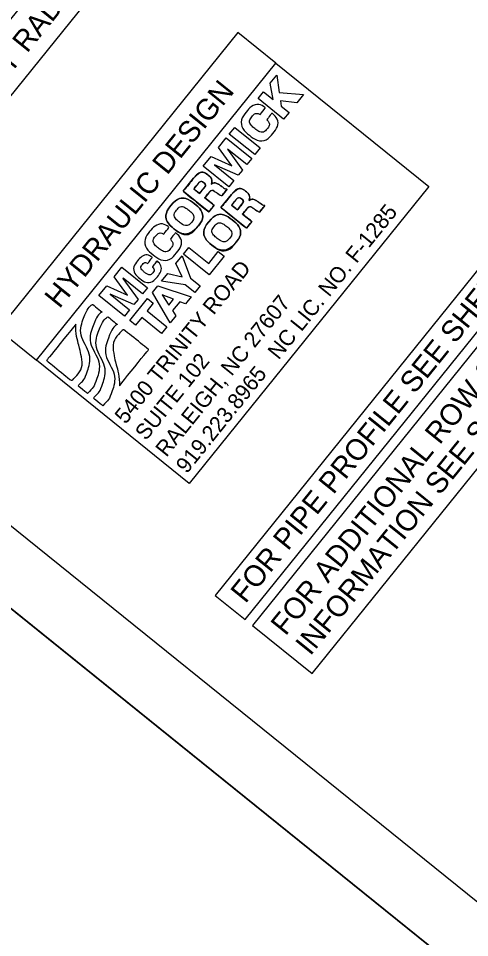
# Model space of a CAD drawing. Extents: x 1487875 to 1489967, y 498345 to 500495.
# Drawn here: x 1489508.5 to 1489628.3, y 499770.6 to 500014.7 of the extents above; entities that cross this region are included whole.
import ezdxf

# ---------------------------------------------------------------- set-up
doc = ezdxf.new("R2010")
doc.units = 0
for name, color, linetype in [('Exist Utilities Gas UG Line SUE LOS B', 7, 'Continuous'), ('Exist Utilities TV UG Cable SUE LOS C', 7, 'Continuous'), ('Exist Utilities Water Fire Hydrant CELL', 7, 'Continuous'), ('Exist Utilities Water Meter CELL', 7, 'Continuous'), ('Prop UG Pow Cables', 7, 'Continuous')]:
    doc.layers.add(name, color=color, linetype=linetype)

msp = doc.modelspace()

# ---------------------------------------------------------------- linework, layer by layer
at = {"layer": 'Exist Utilities TV UG Cable SUE LOS C'}
for points in [[(1488938.86, 500315.83), (1487997.21, 499148.18), (1488814.55, 498489.05), (1489756.18, 499656.68)], [(1488814.55, 498489.05), (1487997.21, 499148.15), (1488813.25, 500160.1), (1488842.5, 500136.51), (1488968.06, 500292.24), (1489756.18, 499656.68)]]:
    msp.add_lwpolyline(points, close=True, dxfattribs=at)
at = {"layer": 'Exist Utilities Water Fire Hydrant CELL'}
msp.add_lwpolyline([(1488842.5, 500136.51), (1488813.25, 500160.1), (1488087.84, 499260.53), (1488879.09, 498569.08), (1489756.18, 499656.68), (1488968.06, 500292.24)], close=True, dxfattribs=at)
msp.add_lwpolyline([(1488842.5, 500136.51), (1488813.25, 500160.1), (1488087.84, 499260.53), (1488879.09, 498569.08), (1489756.18, 499656.68), (1488968.06, 500292.24)], close=True, dxfattribs=at)
at = {"layer": 'Exist Utilities Water Meter CELL'}
for p, q in [((1489575.33, 499997.5), (1489577.1, 499999.7)), ((1489577.1, 499999.7), (1489577.75, 499995.03)), ((1489576.13, 499993.16), (1489575.33, 499997.5)), ((1489572.1, 499993.49), (1489573.53, 499995.26)), ((1489578.89, 499988.01), (1489572.1, 499993.49)), ((1489573.53, 499995.26), (1489576.13, 499993.16)), ((1489577.75, 499995.03), (1489584.15, 499994.53)), ((1489584.15, 499994.53), (1489582.38, 499992.33)), ((1489582.38, 499992.33), (1489578.05, 499992.81)), ((1489578.05, 499992.81), (1489578.23, 499991.47)), ((1489578.23, 499991.47), (1489580.32, 499989.78)), ((1489580.32, 499989.78), (1489578.89, 499988.01)), ((1489564.47, 499984.03), (1489565.9, 499985.8)), ((1489565.9, 499985.8), (1489572.69, 499980.32)), ((1489571.26, 499978.55), (1489564.47, 499984.03)), ((1489561.57, 499980.43), (1489563.67, 499983.04)), ((1489563.67, 499983.04), (1489570.46, 499977.56)), ((1489565.15, 499975.61), (1489561.57, 499980.43)), ((1489563.96, 499980.05), (1489563.95, 499980.03)), ((1489563.95, 499980.03), (1489567.95, 499974.45)), ((1489569.12, 499975.89), (1489563.96, 499980.05)), ((1489572.69, 499980.32), (1489571.26, 499978.55)), ((1489557.56, 499975.46), (1489559.66, 499978.07)), ((1489559.66, 499978.07), (1489565.14, 499975.59)), ((1489560.56, 499975.83), (1489560.54, 499975.81)), ((1489560.54, 499975.81), (1489565.7, 499971.65)), ((1489566.86, 499973.1), (1489560.56, 499975.83)), ((1489570.46, 499977.56), (1489569.12, 499975.89)), ((1489564.36, 499969.98), (1489557.56, 499975.46)), ((1489565.14, 499975.59), (1489565.15, 499975.61)), ((1489567.95, 499974.45), (1489566.86, 499973.1)), ((1489565.7, 499971.65), (1489564.36, 499969.98)), ((1489559.67, 499970.68), (1489559.69, 499970.67)), ((1489563.88, 499969.39), (1489562.47, 499967.64)), ((1489569.72, 499966.35), (1489569.74, 499966.33)), ((1489573.92, 499965.06), (1489572.51, 499963.31)), ((1489552.29, 499952.15), (1489553.72, 499953.92)), ((1489553.72, 499953.92), (1489558.99, 499949.66)), ((1489550.3, 499949.67), (1489551.92, 499951.68)), ((1489551.92, 499951.68), (1489554.18, 499945.77)), ((1489559.09, 499946.67), (1489552.29, 499952.15)), ((1489558.99, 499949.66), (1489561.55, 499952.83)), ((1489563.07, 499951.61), (1489559.09, 499946.67)), ((1489561.55, 499952.83), (1489563.07, 499951.61)), ((1489551.97, 499946.09), (1489550.3, 499949.67)), ((1489533.86, 499946.08), (1489535.97, 499948.69)), ((1489535.97, 499948.69), (1489542.76, 499943.21)), ((1489546.5, 499944.96), (1489548.12, 499946.97)), ((1489548.12, 499946.97), (1489551.97, 499946.09)), ((1489537.45, 499941.25), (1489533.86, 499946.08)), ((1489536.26, 499945.7), (1489536.24, 499945.68)), ((1489536.24, 499945.68), (1489540.25, 499940.09)), ((1489541.42, 499941.54), (1489536.26, 499945.7)), ((1489552.76, 499944), (1489546.5, 499944.96)), ((1489554.18, 499945.77), (1489556.72, 499943.72)), ((1489529.86, 499941.11), (1489531.96, 499943.72)), ((1489531.96, 499943.72), (1489537.43, 499941.24)), ((1489542.76, 499943.21), (1489541.42, 499941.54)), ((1489544.04, 499941.91), (1489545.49, 499943.71)), ((1489548.78, 499933.89), (1489544.04, 499941.91)), ((1489545.49, 499943.71), (1489554.33, 499940.77)), ((1489555.29, 499941.95), (1489552.76, 499944)), ((1489556.72, 499943.72), (1489555.29, 499941.95)), ((1489536.65, 499935.63), (1489529.86, 499941.11)), ((1489532.85, 499941.47), (1489532.84, 499941.46)), ((1489532.84, 499941.46), (1489537.99, 499937.3)), ((1489539.16, 499938.74), (1489532.85, 499941.47)), ((1489537.43, 499941.24), (1489537.45, 499941.25)), ((1489538.06, 499934.49), (1489542.76, 499940.32)), ((1489540.25, 499940.09), (1489539.16, 499938.74)), ((1489542.76, 499940.32), (1489544.28, 499939.09)), ((1489546.65, 499941.29), (1489546.64, 499941.28)), ((1489546.64, 499941.28), (1489548.39, 499938.59)), ((1489549.64, 499940.13), (1489546.65, 499941.29)), ((1489548.39, 499938.59), (1489549.64, 499940.13)), ((1489551.29, 499939.49), (1489549.38, 499937.12)), ((1489552.84, 499938.92), (1489551.29, 499939.49)), ((1489554.33, 499940.77), (1489552.84, 499938.92)), ((1489537.99, 499937.3), (1489536.65, 499935.63)), ((1489544.28, 499939.09), (1489542.64, 499937.06)), ((1489542.64, 499937.06), (1489547.92, 499932.81)), ((1489549.38, 499937.12), (1489550.25, 499935.71)), ((1489539.58, 499933.27), (1489538.06, 499934.49)), ((1489541.22, 499935.29), (1489539.58, 499933.27)), ((1489546.49, 499931.04), (1489541.22, 499935.29)), ((1489550.25, 499935.71), (1489548.78, 499933.89)), ((1489547.92, 499932.81), (1489546.49, 499931.04))]:
    msp.add_line(p, q, dxfattribs=at)
for points in [[(1489457.28, 499933.23), (1489607.58, 500119.6), (1489597.54, 500127.7), (1489447.24, 499941.32)], [(1489513.23, 499923.95), (1489576.85, 500002.83), (1489566.69, 500011.02), (1489503.08, 499932.14)], [(1489513.23, 499923.95), (1489576.85, 500002.83), (1489617.42, 499970.11), (1489553.81, 499891.23)], [(1489568.67, 499855.04), (1489659.41, 499967.55), (1489651.44, 499973.98), (1489560.71, 499861.47)], [(1489586.45, 499840.7), (1489677.19, 499953.22), (1489661.35, 499965.99), (1489570.61, 499853.48)]]:
    msp.add_lwpolyline(points, close=True, dxfattribs=at)
for points in [[(1489572.1, 499993.49), (1489573.53, 499995.26), (1489576.13, 499993.16), (1489575.33, 499997.5), (1489577.1, 499999.7), (1489577.75, 499995.03), (1489584.15, 499994.53), (1489582.38, 499992.33), (1489578.05, 499992.81), (1489578.23, 499991.47), (1489580.32, 499989.78), (1489578.89, 499988.01), (1489572.1, 499993.49)], [(1489564.47, 499984.03), (1489565.9, 499985.8), (1489572.69, 499980.32), (1489571.26, 499978.55), (1489564.47, 499984.03)], [(1489557.56, 499975.46), (1489559.66, 499978.07), (1489565.14, 499975.59), (1489565.15, 499975.61), (1489561.57, 499980.43), (1489563.67, 499983.04), (1489570.46, 499977.56), (1489569.12, 499975.89), (1489563.96, 499980.05), (1489563.95, 499980.03), (1489567.95, 499974.45), (1489566.86, 499973.1), (1489560.56, 499975.83), (1489560.54, 499975.81), (1489565.7, 499971.65), (1489564.36, 499969.98), (1489557.56, 499975.46)], [(1489559.03, 499968.45), (1489557.95, 499967.11), (1489560.42, 499965.11), (1489559, 499963.34), (1489552.2, 499968.82), (1489555, 499972.28)], [(1489556.18, 499970.86), (1489555.05, 499969.45), (1489556.58, 499968.21), (1489557.78, 499969.7)], [(1489569.08, 499964.12), (1489567.99, 499962.77), (1489570.47, 499960.78), (1489569.04, 499959.01), (1489562.25, 499964.49), (1489565.04, 499967.95)], [(1489566.23, 499966.52), (1489565.09, 499965.11), (1489566.62, 499963.88), (1489567.82, 499965.36)], [(1489552.29, 499952.15), (1489553.72, 499953.92), (1489558.99, 499949.66), (1489561.55, 499952.83), (1489563.07, 499951.61), (1489559.09, 499946.67), (1489552.29, 499952.15)], [(1489554.18, 499945.77), (1489556.72, 499943.72), (1489555.29, 499941.95), (1489552.76, 499944), (1489546.5, 499944.96), (1489548.12, 499946.97), (1489551.97, 499946.09), (1489550.3, 499949.67), (1489551.92, 499951.68), (1489554.18, 499945.77)], [(1489529.86, 499941.11), (1489531.96, 499943.72), (1489537.43, 499941.24), (1489537.45, 499941.25), (1489533.86, 499946.08), (1489535.97, 499948.69), (1489542.76, 499943.21), (1489541.42, 499941.54), (1489536.26, 499945.7), (1489536.24, 499945.68), (1489540.25, 499940.09), (1489539.16, 499938.74), (1489532.85, 499941.47), (1489532.84, 499941.46), (1489537.99, 499937.3), (1489536.65, 499935.63), (1489529.86, 499941.11)], [(1489544.04, 499941.91), (1489545.49, 499943.71), (1489554.33, 499940.77), (1489552.84, 499938.92), (1489551.29, 499939.49), (1489549.38, 499937.12), (1489550.25, 499935.71), (1489548.78, 499933.89), (1489544.04, 499941.91)], [(1489544.28, 499939.09), (1489542.64, 499937.06), (1489547.92, 499932.81), (1489546.49, 499931.04), (1489541.22, 499935.29), (1489539.58, 499933.27), (1489538.06, 499934.49), (1489542.76, 499940.32), (1489544.28, 499939.09)], [(1489548.39, 499938.59), (1489549.64, 499940.13), (1489546.65, 499941.29), (1489546.64, 499941.28), (1489548.39, 499938.59)]]:
    msp.add_lwpolyline(points, dxfattribs=at)
for points in [[(1489572.64, 499989.2), (1489571.88, 499989.66), (1489571.09, 499989.42), (1489570.49, 499988.68), (1489569.57, 499987.53), (1489570.23, 499986.28), (1489571.24, 499985.47), (1489572.24, 499984.65), (1489573.61, 499984.28), (1489574.53, 499985.42), (1489575.19, 499986.25), (1489575.1, 499987.11), (1489574.38, 499987.8), (1489574.38, 499987.8), (1489575.8, 499989.57), (1489575.8, 499989.57), (1489577.48, 499988.07), (1489577.47, 499985.95), (1489576.08, 499984.23), (1489574.42, 499982.18), (1489571.78, 499982.11), (1489569.81, 499983.7), (1489567.84, 499985.29), (1489567.34, 499987.89), (1489569, 499989.94), (1489570.18, 499991.41), (1489572.4, 499992.24), (1489574.07, 499990.97), (1489574.07, 499990.97), (1489572.64, 499989.2), (1489572.64, 499989.2)], [(1489572.64, 499989.2), (1489571.88, 499989.66), (1489571.09, 499989.42), (1489570.49, 499988.68), (1489569.57, 499987.53), (1489570.23, 499986.28), (1489571.24, 499985.47), (1489572.24, 499984.65), (1489573.61, 499984.28), (1489574.53, 499985.42), (1489575.19, 499986.25), (1489575.1, 499987.11), (1489574.38, 499987.8), (1489574.38, 499987.8), (1489575.8, 499989.57), (1489575.8, 499989.57), (1489577.48, 499988.07), (1489577.47, 499985.95), (1489576.08, 499984.23), (1489574.42, 499982.18), (1489571.78, 499982.11), (1489569.81, 499983.7), (1489567.84, 499985.29), (1489567.34, 499987.89), (1489569, 499989.94), (1489570.18, 499991.41), (1489572.4, 499992.24), (1489574.07, 499990.97), (1489574.07, 499990.97), (1489572.64, 499989.2), (1489572.64, 499989.2)], [(1489552.2, 499968.82), (1489552.2, 499968.82), (1489555, 499972.28), (1489555, 499972.28), (1489555.96, 499973.48), (1489557.46, 499974.23), (1489558.83, 499973.12), (1489559.56, 499972.53), (1489559.97, 499971.62), (1489559.67, 499970.68), (1489559.67, 499970.68), (1489559.69, 499970.67), (1489559.69, 499970.67), (1489560.45, 499971.25), (1489561.42, 499970.81), (1489562.12, 499970.34), (1489562.42, 499970.13), (1489563.44, 499969.35), (1489563.88, 499969.39), (1489563.88, 499969.39), (1489562.47, 499967.64), (1489562.47, 499967.64), (1489562.12, 499967.67), (1489561.43, 499968.18), (1489561.22, 499968.32), (1489560.5, 499968.82), (1489559.7, 499969.28), (1489559.03, 499968.45), (1489559.03, 499968.45), (1489557.95, 499967.11), (1489557.95, 499967.11), (1489557.95, 499967.11), (1489560.42, 499965.11), (1489560.42, 499965.11), (1489560.42, 499965.11), (1489559, 499963.34), (1489559, 499963.34), (1489559, 499963.34), (1489552.2, 499968.82), (1489552.2, 499968.82)], [(1489555, 499972.28), (1489555.96, 499973.48), (1489557.46, 499974.23), (1489558.83, 499973.12), (1489559.56, 499972.53), (1489559.97, 499971.62), (1489559.67, 499970.68)], [(1489556.58, 499968.21), (1489556.58, 499968.21), (1489557.78, 499969.7), (1489557.78, 499969.7), (1489558.21, 499970.23), (1489558.15, 499970.74), (1489557.64, 499971.16), (1489557.13, 499971.57), (1489556.58, 499971.35), (1489556.18, 499970.86), (1489556.18, 499970.86), (1489555.05, 499969.45), (1489555.05, 499969.45), (1489555.05, 499969.45), (1489556.58, 499968.21), (1489556.58, 499968.21)], [(1489557.78, 499969.7), (1489558.21, 499970.23), (1489558.15, 499970.74), (1489557.64, 499971.16), (1489557.13, 499971.57), (1489556.58, 499971.35), (1489556.18, 499970.86)], [(1489559.69, 499970.67), (1489560.45, 499971.25), (1489561.42, 499970.81), (1489562.12, 499970.34), (1489562.42, 499970.13), (1489563.44, 499969.35), (1489563.88, 499969.39)], [(1489562.47, 499967.64), (1489562.12, 499967.67), (1489561.43, 499968.18), (1489561.22, 499968.32), (1489560.5, 499968.82), (1489559.7, 499969.28), (1489559.03, 499968.45)], [(1489562.25, 499964.49), (1489562.25, 499964.49), (1489565.04, 499967.95), (1489565.04, 499967.95), (1489566.01, 499969.15), (1489567.5, 499969.89), (1489568.87, 499968.79), (1489569.61, 499968.2), (1489570.02, 499967.29), (1489569.72, 499966.35), (1489569.72, 499966.35), (1489569.74, 499966.33), (1489569.74, 499966.33), (1489570.49, 499966.92), (1489571.47, 499966.48), (1489572.16, 499966.01), (1489572.46, 499965.8), (1489573.48, 499965.02), (1489573.92, 499965.06), (1489573.92, 499965.06), (1489572.51, 499963.31), (1489572.51, 499963.31), (1489572.16, 499963.34), (1489571.47, 499963.85), (1489571.26, 499963.99), (1489570.54, 499964.49), (1489569.74, 499964.94), (1489569.08, 499964.12), (1489569.08, 499964.12), (1489567.99, 499962.77), (1489567.99, 499962.77), (1489567.99, 499962.77), (1489570.47, 499960.78), (1489570.47, 499960.78), (1489570.47, 499960.78), (1489569.04, 499959.01), (1489569.04, 499959.01), (1489569.04, 499959.01), (1489562.25, 499964.49), (1489562.25, 499964.49)], [(1489565.04, 499967.95), (1489566.01, 499969.15), (1489567.5, 499969.89), (1489568.87, 499968.79), (1489569.61, 499968.2), (1489570.02, 499967.29), (1489569.72, 499966.35)], [(1489548.93, 499965.06), (1489550.66, 499967.2), (1489553.21, 499967.14), (1489555.18, 499965.55), (1489557.15, 499963.96), (1489557.74, 499961.49), (1489556.01, 499959.35), (1489554.29, 499957.21), (1489551.74, 499957.26), (1489549.77, 499958.85), (1489547.8, 499960.44), (1489547.21, 499962.92), (1489548.93, 499965.06)], [(1489548.93, 499965.06), (1489550.66, 499967.2), (1489553.21, 499967.14), (1489555.18, 499965.55), (1489557.15, 499963.96), (1489557.74, 499961.49), (1489556.01, 499959.35), (1489555.78, 499959.06), (1489555.53, 499958.8), (1489555.26, 499958.59)], [(1489566.62, 499963.88), (1489566.62, 499963.88), (1489567.82, 499965.36), (1489567.82, 499965.36), (1489568.25, 499965.9), (1489568.2, 499966.41), (1489567.68, 499966.83), (1489567.18, 499967.23), (1489566.63, 499967.02), (1489566.23, 499966.52), (1489566.23, 499966.52), (1489565.09, 499965.11), (1489565.09, 499965.11), (1489565.09, 499965.11), (1489566.62, 499963.88), (1489566.62, 499963.88)], [(1489567.82, 499965.36), (1489568.25, 499965.9), (1489568.2, 499966.41), (1489567.68, 499966.83), (1489567.18, 499967.23), (1489566.63, 499967.02), (1489566.23, 499966.52)], [(1489569.74, 499966.33), (1489570.49, 499966.92), (1489571.47, 499966.48), (1489572.16, 499966.01), (1489572.46, 499965.8), (1489573.48, 499965.02), (1489573.92, 499965.06)], [(1489555.26, 499958.59), (1489553.6, 499957.25), (1489551.47, 499957.48), (1489549.77, 499958.85), (1489547.8, 499960.44), (1489547.21, 499962.92), (1489548.93, 499965.06)], [(1489554.49, 499960.58), (1489555.41, 499961.72), (1489554.76, 499962.97), (1489553.75, 499963.78), (1489552.74, 499964.6), (1489551.38, 499964.97), (1489550.46, 499963.83), (1489549.53, 499962.69), (1489550.19, 499961.44), (1489551.2, 499960.62), (1489552.21, 499959.81), (1489553.57, 499959.43), (1489554.49, 499960.58)], [(1489554.49, 499960.58), (1489555.41, 499961.72), (1489554.76, 499962.97), (1489553.75, 499963.78), (1489552.74, 499964.6), (1489551.38, 499964.97), (1489550.46, 499963.83), (1489549.53, 499962.69), (1489550.19, 499961.44), (1489551.2, 499960.62), (1489552.21, 499959.81), (1489553.57, 499959.43), (1489554.49, 499960.58)], [(1489572.51, 499963.31), (1489572.16, 499963.34), (1489571.47, 499963.85), (1489571.26, 499963.99), (1489570.54, 499964.49), (1489569.74, 499964.94), (1489569.08, 499964.12)], [(1489558.99, 499960.74), (1489560.71, 499962.88), (1489563.26, 499962.82), (1489565.23, 499961.23), (1489567.2, 499959.64), (1489567.79, 499957.17), (1489566.07, 499955.03), (1489564.34, 499952.88), (1489561.79, 499952.94), (1489559.82, 499954.53), (1489557.85, 499956.12), (1489557.26, 499958.6), (1489558.99, 499960.74)], [(1489558.99, 499960.74), (1489560.71, 499962.88), (1489563.26, 499962.82), (1489565.23, 499961.23), (1489567.2, 499959.64), (1489567.79, 499957.17), (1489566.07, 499955.03), (1489565.83, 499954.73), (1489565.58, 499954.48), (1489565.31, 499954.27)], [(1489547.04, 499957.46), (1489546.28, 499957.91), (1489545.49, 499957.67), (1489544.89, 499956.93), (1489543.97, 499955.79), (1489544.63, 499954.54), (1489545.63, 499953.72), (1489546.64, 499952.91), (1489548.01, 499952.53), (1489548.93, 499953.68), (1489549.59, 499954.5), (1489549.5, 499955.36), (1489548.78, 499956.06), (1489548.78, 499956.06), (1489550.2, 499957.83), (1489550.2, 499957.83), (1489551.88, 499956.32), (1489551.87, 499954.21), (1489550.48, 499952.49), (1489548.82, 499950.43), (1489546.18, 499950.36), (1489544.21, 499951.95), (1489542.24, 499953.54), (1489541.74, 499956.14), (1489543.4, 499958.2), (1489544.58, 499959.66), (1489546.8, 499960.5), (1489548.47, 499959.23), (1489548.47, 499959.23), (1489547.04, 499957.46), (1489547.04, 499957.46)], [(1489547.04, 499957.46), (1489546.28, 499957.91), (1489545.49, 499957.67), (1489544.89, 499956.93), (1489543.97, 499955.79), (1489544.63, 499954.54), (1489545.63, 499953.72), (1489546.64, 499952.91), (1489548.01, 499952.53), (1489548.93, 499953.68), (1489549.59, 499954.5), (1489549.5, 499955.36), (1489548.78, 499956.06), (1489548.78, 499956.06), (1489550.2, 499957.83), (1489550.2, 499957.83), (1489551.88, 499956.32), (1489551.87, 499954.21), (1489550.48, 499952.49), (1489548.82, 499950.43), (1489546.18, 499950.36), (1489544.21, 499951.95), (1489542.24, 499953.54), (1489541.74, 499956.14), (1489543.4, 499958.2), (1489544.58, 499959.66), (1489546.8, 499960.5), (1489548.47, 499959.23), (1489548.47, 499959.23), (1489547.04, 499957.46), (1489547.04, 499957.46)], [(1489565.31, 499954.27), (1489563.65, 499952.93), (1489561.52, 499953.16), (1489559.82, 499954.53), (1489557.85, 499956.12), (1489557.26, 499958.6), (1489558.99, 499960.74)], [(1489564.54, 499956.25), (1489565.46, 499957.4), (1489564.81, 499958.65), (1489563.8, 499959.46), (1489562.79, 499960.28), (1489561.43, 499960.65), (1489560.51, 499959.51), (1489559.59, 499958.37), (1489560.24, 499957.12), (1489561.25, 499956.3), (1489562.26, 499955.49), (1489563.62, 499955.11), (1489564.54, 499956.25)], [(1489564.54, 499956.25), (1489565.46, 499957.4), (1489564.81, 499958.65), (1489563.8, 499959.46), (1489562.79, 499960.28), (1489561.43, 499960.65), (1489560.51, 499959.51), (1489559.59, 499958.37), (1489560.24, 499957.12), (1489561.25, 499956.3), (1489562.26, 499955.49), (1489563.62, 499955.11), (1489564.54, 499956.25)], [(1489542.81, 499949.67), (1489542.38, 499950), (1489541.78, 499949.86), (1489541.45, 499949.46), (1489540.73, 499948.55), (1489541.38, 499947.79), (1489542.07, 499947.23), (1489542.7, 499946.72), (1489543.58, 499946.47), (1489544.14, 499947.15), (1489544.59, 499947.71), (1489544.5, 499948.26), (1489544.03, 499948.76), (1489544.03, 499948.76), (1489545.3, 499950.33), (1489545.3, 499950.33), (1489546.51, 499949.12), (1489546.44, 499947.48), (1489545.38, 499946.16), (1489544.18, 499944.68), (1489542.27, 499944.4), (1489540.76, 499945.62), (1489539.19, 499946.88), (1489538.87, 499948.79), (1489540.16, 499950.38), (1489541.15, 499951.6), (1489542.68, 499952.18), (1489544.07, 499951.24), (1489544.07, 499951.24), (1489542.81, 499949.67), (1489542.81, 499949.67)], [(1489542.81, 499949.67), (1489542.38, 499950), (1489541.78, 499949.86), (1489541.45, 499949.46), (1489540.73, 499948.55), (1489541.38, 499947.79), (1489542.07, 499947.23), (1489542.7, 499946.72), (1489543.58, 499946.47), (1489544.14, 499947.15), (1489544.59, 499947.71), (1489544.5, 499948.26), (1489544.03, 499948.76), (1489544.03, 499948.76), (1489545.3, 499950.33), (1489545.3, 499950.33), (1489546.51, 499949.12), (1489546.44, 499947.48), (1489545.38, 499946.16), (1489544.18, 499944.68), (1489542.27, 499944.4), (1489540.76, 499945.62), (1489539.19, 499946.88), (1489538.87, 499948.79), (1489540.16, 499950.38), (1489541.15, 499951.6), (1489542.68, 499952.18), (1489544.07, 499951.24), (1489544.07, 499951.24), (1489542.81, 499949.67), (1489542.81, 499949.67)], [(1489526.82, 499915.08), (1489527.53, 499915.95), (1489528.39, 499916.55), (1489529.21, 499918.63), (1489530.75, 499923.42), (1489526.65, 499928.68), (1489528.43, 499933.5), (1489529.47, 499935.95), (1489530.65, 499936.76), (1489530.65, 499936.76), (1489530.65, 499936.76), (1489528.14, 499938.79), (1489528.14, 499938.79), (1489528.14, 499938.79), (1489526.95, 499937.98), (1489525.91, 499935.53), (1489524.14, 499930.71), (1489528.24, 499925.45), (1489526.7, 499920.65), (1489525.88, 499918.58), (1489525.01, 499917.98), (1489524.31, 499917.11), (1489524.31, 499917.11), (1489526.82, 499915.08), (1489526.82, 499915.08)], [(1489526.82, 499915.08), (1489527.53, 499915.95), (1489528.39, 499916.55), (1489529.21, 499918.63), (1489530.75, 499923.42), (1489526.65, 499928.68), (1489528.43, 499933.5), (1489529.47, 499935.95), (1489530.65, 499936.76), (1489530.65, 499936.76), (1489530.65, 499936.76), (1489528.14, 499938.79), (1489528.14, 499938.79), (1489528.14, 499938.79), (1489526.95, 499937.98), (1489525.91, 499935.53), (1489524.14, 499930.71), (1489528.24, 499925.45), (1489526.7, 499920.65), (1489525.88, 499918.58), (1489525.01, 499917.98), (1489524.31, 499917.11), (1489524.31, 499917.11), (1489526.82, 499915.08), (1489526.82, 499915.08)], [(1489530.89, 499911.8), (1489531.59, 499912.68), (1489532.46, 499913.27), (1489533.27, 499915.35), (1489534.82, 499920.14), (1489530.72, 499925.41), (1489532.49, 499930.22), (1489533.53, 499932.67), (1489534.71, 499933.49), (1489534.71, 499933.49), (1489534.71, 499933.49), (1489532.2, 499935.51), (1489532.2, 499935.51), (1489532.2, 499935.51), (1489531.02, 499934.7), (1489529.98, 499932.25), (1489528.2, 499927.43), (1489532.3, 499922.17), (1489530.76, 499917.38), (1489529.94, 499915.3), (1489529.08, 499914.7), (1489528.37, 499913.83), (1489528.37, 499913.83), (1489530.89, 499911.8), (1489530.89, 499911.8)], [(1489530.89, 499911.8), (1489531.59, 499912.68), (1489532.46, 499913.27), (1489533.27, 499915.35), (1489534.82, 499920.14), (1489530.72, 499925.41), (1489532.49, 499930.22), (1489533.53, 499932.67), (1489534.71, 499933.49), (1489534.71, 499933.49), (1489534.71, 499933.49), (1489532.2, 499935.51), (1489532.2, 499935.51), (1489532.2, 499935.51), (1489531.02, 499934.7), (1489529.98, 499932.25), (1489528.2, 499927.43), (1489532.3, 499922.17), (1489530.76, 499917.38), (1489529.94, 499915.3), (1489529.08, 499914.7), (1489528.37, 499913.83), (1489528.37, 499913.83), (1489530.89, 499911.8), (1489530.89, 499911.8)], [(1489523.69, 499933.48), (1489523.58, 499931.12), (1489524.75, 499927.17), (1489525.02, 499925.82), (1489525.68, 499922.48), (1489524.45, 499920.27), (1489522.61, 499918.48), (1489522.61, 499918.48), (1489515.93, 499923.86), (1489515.93, 499923.86), (1489515.93, 499923.86), (1489523.69, 499933.48), (1489523.69, 499933.48)], [(1489523.69, 499933.48), (1489523.58, 499931.12), (1489524.75, 499927.17), (1489525.02, 499925.82), (1489525.68, 499922.48), (1489524.45, 499920.27), (1489522.61, 499918.48), (1489522.61, 499918.48), (1489515.93, 499923.86), (1489515.93, 499923.86), (1489515.93, 499923.86), (1489523.69, 499933.48), (1489523.69, 499933.48)], [(1489535.29, 499917.15), (1489535.39, 499919.51), (1489534.22, 499923.46), (1489533.95, 499924.81), (1489533.29, 499928.16), (1489534.53, 499930.37), (1489536.36, 499932.16), (1489536.36, 499932.16), (1489543.04, 499926.77), (1489543.04, 499926.77), (1489543.04, 499926.77), (1489535.29, 499917.15), (1489535.29, 499917.15)], [(1489535.29, 499917.15), (1489535.39, 499919.51), (1489534.22, 499923.46), (1489533.95, 499924.81), (1489533.29, 499928.16), (1489534.53, 499930.37), (1489536.36, 499932.16), (1489536.36, 499932.16), (1489543.04, 499926.77), (1489543.04, 499926.77), (1489543.04, 499926.77), (1489535.29, 499917.15), (1489535.29, 499917.15)]]:
    msp.add_open_spline(points, degree=3, dxfattribs=at)
at = {"layer": 'Prop UG Pow Cables'}
msp.add_lwpolyline([(1488727.56, 498345.32), (1489784.38, 499655.78), (1488932.01, 500343.17), (1487875.19, 499032.7)], close=True, dxfattribs=at)

# ---------------------------------------------------------------- texts
at = {"layer": 'Exist Utilities Gas UG Line SUE LOS B'}
for s, p in [('NOTE:  ALL DRIVEWAY RADII 10 FT UNLESS OTHERWISE NOTED.', (1489457.51, 499939.3)), ('HYDRAULIC DESIGN', (1489519.35, 499937.45)), ('FOR PIPE PROFILE SEE SHEET 2D-1.', (1489568.75, 499859.12)), ('FOR ADDITIONAL ROW & EASEMENT ', (1489579.4, 499850.53)), ('INFORMATION SEE SHEET 5A.', (1489585.97, 499845.23))]:
    msp.add_text(s, height=5.625, rotation=51.1156, dxfattribs=at).set_placement(p)
at = {"layer": 'Exist Utilities Water Meter CELL'}
for s, height, p in [('919.223.8965   NC LIC. NO. F-1285', 4.1773, (1489553.18, 499893.63)), ('5400 TRINITY ROAD', 4.1773, (1489536.92, 499906.75)), ('RALEIGH, NC 27607', 4.1773, (1489547.76, 499898)), ('SUITE 102', 4.177, (1489542.34, 499902.38))]:
    msp.add_text(s, height=height, rotation=51.1156, dxfattribs=at).set_placement(p)

doc.saveas('drawing.dxf')
